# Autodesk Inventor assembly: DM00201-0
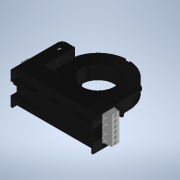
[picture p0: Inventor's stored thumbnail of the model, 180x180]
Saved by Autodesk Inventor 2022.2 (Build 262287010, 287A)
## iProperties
Created: 2022-10
Part Number: DM00201-0
Document SubType Name: Assembly
Designer: zambolin
Title: C:\Users\zambolin\Desktop\PRODOTTI\T203PMXXX-MU\3D\DM00201-0.stp
Author: zambolin
Sending System: Autodesk Inventor 2022
Preprocessor: ST-DEVELOPER v18.1
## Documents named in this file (8)
- C:\Users\zambolin\Desktop\PRODOTTI\T203PMXXX-MU\3D\DM00201-0.iam
- C:\Users\zambolin\Desktop\PRODOTTI\T203PMXXX-MU\3D\PM00540-0.ipt
- C:\Users\zambolin\Desktop\PRODOTTI\T203PMXXX-MU\3D\PM00541-1.ipt
- C:\Users\zambolin\Desktop\PRODOTTI\T203PMXXX-MU\3D\mstb_2.5-3-st.ipt
- C:\Users\zambolin\Desktop\PRODOTTI\T203PMXXX-MU\3D\mstb_2.5-3-st_CPY.ipt
- C:\Users\zambolin\Desktop\PRODOTTI\T203PMXXX-MU\3D\mstb_2.5-3-st_CPY1.ipt
- C:\Users\zambolin\Desktop\PRODOTTI\T203PMXXX-MU\3D\mstb_2.5-3-st_CPY1_CPY.ipt
- C:\Users\zambolin\Desktop\PRODOTTI\T203PMXXX-MU\3D\CIRCUITO STAMPATO.iam
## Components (7 placed, 7 different names)
1. PM00540-0:1
2. PM00541-1:1
3. mstb_2.5-3-st:1
4. mstb_2.5-3-st_CPY:1
5. mstb_2.5-3-st_CPY1:1
6. mstb_2.5-3-st_CPY1_CPY:1
7. CIRCUITO STAMPATO:1 [sub-assembly]
